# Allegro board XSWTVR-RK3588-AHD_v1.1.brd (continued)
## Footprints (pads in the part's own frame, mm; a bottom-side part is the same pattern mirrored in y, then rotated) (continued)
IC_SOT_223_1P2V
  rect 2.2x1.1 smd: 1(3.099,-2.3) 2(3.099,0) 3(3.099,2.3)
  rect 2.2x3.5 smd: 4(-3.099,0)
IC_SSOP_16
  oval 0.574x2.038 smd: 1(-4.445,-2.769) 2(-3.175,-2.769) 3(-1.905,-2.769) 4(-0.635,-2.769) 5(0.635,-2.769) 6(1.905,-2.769) 7(3.175,-2.769) 8(4.445,-2.769) 9(4.445,2.769) 10(3.175,2.769) 11(1.905,2.769) 12(0.635,2.769) 13(-0.635,2.769) 14(-1.905,2.769) 15(-3.175,2.769) 16(-4.445,2.769)
IC_TQFP128
  oval 0.3x1.5 smd: 1(-6.25,-7.75) 32(6.25,-7.75) 65(6.25,7.75) 96(-6.25,7.75)
  oval 0.2x1.5 smd: 2(-5.8,-7.75) 3(-5.4,-7.75) 4(-5,-7.75) 5(-4.6,-7.75) 6(-4.2,-7.75) 7(-3.8,-7.75) 8(-3.4,-7.75) 9(-3,-7.75) 10(-2.6,-7.75) 11(-2.2,-7.75) 12(-1.8,-7.75) 13(-1.4,-7.75) 14(-1,-7.75) 15(-0.6,-7.75) 16(-0.2,-7.75) 17(0.2,-7.75) 18(0.6,-7.75) 19(1,-7.75) 20(1.4,-7.75) 21(1.8,-7.75) 22(2.2,-7.75) 23(2.6,-7.75) 24(3,-7.75) 25(3.4,-7.75) 26(3.8,-7.75) 27(4.2,-7.75) 28(4.6,-7.75) 29(5,-7.75) 30(5.4,-7.75) 31(5.8,-7.75) 66(5.8,7.75) 67(5.4,7.75) 68(5,7.75) 69(4.6,7.75) 70(4.2,7.75) 71(3.8,7.75) 72(3.4,7.75) 73(3,7.75) 74(2.6,7.75) 75(2.2,7.75) 76(1.8,7.75) 77(1.4,7.75) 78(1,7.75) 79(0.6,7.75) 80(0.2,7.75) 81(-0.2,7.75) 82(-0.6,7.75) 83(-1,7.75) 84(-1.4,7.75) 85(-1.8,7.75) 86(-2.2,7.75) 87(-2.6,7.75) 88(-3,7.75) 89(-3.4,7.75) 90(-3.8,7.75) 91(-4.2,7.75) 92(-4.6,7.75) 93(-5,7.75) 94(-5.4,7.75) 95(-5.8,7.75)
  oval 1.5x0.3 smd: 33(7.75,-6.25) 64(7.75,6.25) 97(-7.75,6.25) 128(-7.75,-6.25)
  oval 1.5x0.2 smd: 34(7.75,-5.8) 35(7.75,-5.4) 36(7.75,-5) 37(7.75,-4.6) 38(7.75,-4.2) 39(7.75,-3.8) 40(7.75,-3.4) 41(7.75,-3) 42(7.75,-2.6) 43(7.75,-2.2) 44(7.75,-1.8) 45(7.75,-1.4) 46(7.75,-1) 47(7.75,-0.6) 48(7.75,-0.2) 49(7.75,0.2) 50(7.75,0.6) 51(7.75,1) 52(7.75,1.4) 53(7.75,1.8) 54(7.75,2.2) 55(7.75,2.6) 56(7.75,3) 57(7.75,3.4) 58(7.75,3.8) 59(7.75,4.2) 60(7.75,4.6) 61(7.75,5) 62(7.75,5.4) 63(7.75,5.8) 98(-7.75,5.8) 99(-7.75,5.4) 100(-7.75,5) 101(-7.75,4.6) 102(-7.75,4.2) 103(-7.75,3.8) 104(-7.75,3.4) 105(-7.75,3) 106(-7.75,2.6) 107(-7.75,2.2) 108(-7.75,1.8) 109(-7.75,1.4) 110(-7.75,1) 111(-7.75,0.6) 112(-7.75,0.2) 113(-7.75,-0.2) 114(-7.75,-0.6) 115(-7.75,-1) 116(-7.75,-1.4) 117(-7.75,-1.8) 118(-7.75,-2.2) 119(-7.75,-2.6) 120(-7.75,-3) 121(-7.75,-3.4) 122(-7.75,-3.8) 123(-7.75,-4.2) 124(-7.75,-4.6) 125(-7.75,-5) 126(-7.75,-5.4) 127(-7.75,-5.8)
  rect 6.35x6.35 smd: 129(0,0)
IC_WQFN_10
  rect 0.2x0.75 smd: 1(-0.2,-0.565)
  rect 0.2x0.665 smd: 2(0.2,-0.608) 6(0.2,0.608) 7(-0.2,0.608)
  rect 0.665x0.2 smd: 3(0.832,-0.4) 4(0.832,0) 5(0.832,0.4) 8(-0.832,0.4) 9(-0.832,0) 10(-0.832,-0.4)
L0402
  rect 0.5x0.5 smd: 1(-0.4,0) 2(0.4,0)
L2520
  rect 0.85x2 smd: 1(-1.15,0) 2(1.15,0)
L_6030
  rect 2.15x3.32 smd: 1(-2.913,0) 2(2.913,0)
LED_0603
  rect 0.8x0.8 smd: 1(-0.75,0) 2(0.75,0)
LEDX2
  rect 1.524x1.524 hole 0.66: 1(0,0) 3(0,-2.5)
  round 1.524 hole 0.66: 2(2.5,0) 4(2.5,-2.5)
M2_M_KEY
  rect 0.3x1.55 smd: 1(-9.25,5.275) 2(-9,-2.275) 3(-8.75,5.275) 4(-8.5,-2.275) 5(-8.25,5.275) 6(-8,-2.275) 7(-7.75,5.275) 8(-7.5,-2.275) 9(-7.25,5.275) 10(-7,-2.275) 11(-6.75,5.275) 20(-4.5,-2.275) 21(-4.25,5.275) 22(-4,-2.275) 23(-3.75,5.275) 24(-3.5,-2.275) 25(-3.25,5.275) 26(-3,-2.275) 27(-2.75,5.275) 28(-2.5,-2.275) 29(-2.25,5.275) 30(-2,-2.275) 31(-1.75,5.275) 32(-1.5,-2.275) 33(-1.25,5.275) 34(-1,-2.275) 35(-0.75,5.275) 36(-0.5,-2.275) 37(-0.25,5.275) 38(0,-2.275) 39(0.25,5.275) 40(0.5,-2.275) 41(0.75,5.275) 42(1,-2.275) 43(1.25,5.275) 44(1.5,-2.275) 45(1.75,5.275) 46(2,-2.275) 47(2.25,5.275) 48(2.5,-2.275) 49(2.75,5.275) 50(3,-2.275) 51(3.25,5.275) 52(3.5,-2.275) 53(3.75,5.275) 54(4,-2.275) 55(4.25,5.275) 56(4.5,-2.275) 57(4.75,5.275) 58(5,-2.275) 59(5.25,5.275) 60(5.5,-2.275) 61(5.75,5.275) 62(6,-2.275) 63(6.25,5.275) 64(6.5,-2.275) 65(6.75,5.275) 66(7,-2.275) 67(7.25,5.275) 68(7.5,-2.275) 69(7.75,5.275) 70(8,-2.275) 71(8.25,5.275) 72(8.5,-2.275) 73(8.75,5.275) 74(9,-2.275) 75(9.25,5.275)
  rect 1.2x2.75 smd: 76(-10.35,4.5) 77(10.35,4.5)
  round 4.5 hole 3.5: 78(0,-49.8)
M2_SSD_2240_2280
  rect 0.3x1.55 smd: 1(0.75,5.278) 2(1,-2.272) 3(1.25,5.278) 4(1.5,-2.272) 5(1.75,5.278) 6(2,-2.272) 7(2.25,5.278) 8(2.5,-2.272) 9(2.75,5.278) 10(3,-2.272) 11(3.25,5.278) 12(3.5,-2.272) 13(3.75,5.278) 14(4,-2.272) 15(4.25,5.278) 16(4.5,-2.272) 17(4.75,5.278) 18(5,-2.272) 19(5.25,5.278) 20(5.5,-2.272) 21(5.75,5.278) 22(6,-2.272) 23(6.25,5.278) 24(6.5,-2.272) 25(6.75,5.278) 26(7,-2.272) 27(7.25,5.278) 28(7.5,-2.272) 29(7.75,5.278) 30(8,-2.272) 31(8.25,5.278) 32(8.5,-2.272) 33(8.75,5.278) 34(9,-2.272) 35(9.25,5.278) 36(9.5,-2.272) 37(9.75,5.278) 38(10,-2.272) 39(10.25,5.278) 40(10.5,-2.272) 41(10.75,5.278) 42(11,-2.272) 43(11.25,5.278) 44(11.5,-2.272) 45(11.75,5.278) 46(12,-2.272) 47(12.25,5.278) 48(12.5,-2.272) 49(12.75,5.278) 50(13,-2.272) 51(13.25,5.278) 52(13.5,-2.272) 53(13.75,5.278) 54(14,-2.272) 55(14.25,5.278) 56(14.5,-2.272) 57(14.75,5.278) 58(15,-2.272) 67(17.25,5.278) 68(17.5,-2.272) 69(17.75,5.278) 70(18,-2.272) 71(18.25,5.278) 72(18.5,-2.272) 73(18.75,5.278) 74(19,-2.272) 75(19.25,5.278)
  rect 1.2x2.75 smd: 76(-0.35,4.503) 77(20.35,4.503)
  round 6 hole 3.5: 78(10.2,-40.247) 79(10.2,-78.247)
MARK
  round 1 smd: 1(0,0)
MODEL_SKG123NR
  rect 1.9x0.8 smd: 1(-6.1,8.1) 2(-6.1,7) 3(-6.1,5.9) 4(-6.1,4.8) 5(-6.1,3.7) 6(-6.1,2.6) 7(-6.1,1.5) 8(-6.1,-1.5) 9(-6.1,-2.6) 10(-6.1,-3.7) 11(-6.1,-4.8) 12(-6.1,-5.9) 13(6.1,-5.9) 14(6.1,-4.8) 15(6.1,-3.7) 16(6.1,-2.6) 17(6.1,-1.5) 18(6.1,1.5) 19(6.1,2.6) 20(6.1,3.7) 21(6.1,4.8) 22(6.1,5.9) 23(6.1,7) 24(6.1,8.1)
MODLE_65X65MM_256P
  oval 0.7x1.2 smd: 1(0,0) 64(63,0.044)
  oval 0.7x2 smd: 2(1,0.03) 3(2,0.03) 4(3,0.03) 5(4,0.03) 6(5,0.03) 7(6,0.03) 8(7,0.03) 9(8,0.03) 10(9,0.03) 11(10,0.03) 12(11,0.03) 13(12,0.03) 14(13,0.03) 15(14,0.03) 16(15,0.03) 17(16,0.03) 18(17,0.03) 19(18,0.03) 20(19,0.03) 21(20,0.03) 22(21,0.03) 23(22,0.03) 24(23,0.03) 25(24,0.03) 26(25,0.03) 27(26,0.03) 28(27,0.03) 29(28,0.03) 30(29,0.03) 31(30,0.03) 32(31,0.03) 33(32,0.03) 34(33,0.03) 35(34,0.03) 36(35,0.03) 37(36,0.03) 38(37,0.03) 39(38,0.03) 40(39,0.03) 41(40,0.03) 42(41,0.03) 43(42,0.03) 44(43,0.03) 45(44,0.03) 46(45,0.03) 47(46,0.03) 48(47,0.03) 49(48,0.03) 50(49,0.03) 51(50,0.03) 52(51,0.03) 53(52,0.03) 54(53,0.03) 55(54,0.03) 56(55,0.03) 57(56,0.03) 58(57,0.03) 59(58,0.03) 60(59,0.03) 61(60,0.03) 62(61,0.03) 63(62,0.03) 130(62,65.13) 131(61,65.13) 132(60,65.13) 133(59,65.13) 134(58,65.13) 135(57,65.13) 136(56,65.13) 137(55,65.13) 138(54,65.13) 139(53,65.13) 140(52,65.13) 141(51,65.13) 142(50,65.13) 143(49,65.13) 144(48,65.13) 145(47,65.13) 146(46,65.13) 147(45,65.13) 148(44,65.13) 149(43,65.13) 150(42,65.13) 151(41,65.13) 152(40,65.13) 153(39,65.13) 154(38,65.13) 155(37,65.13) 156(36,65.13) 157(35,65.13) 158(34,65.13) 159(33,65.13) 160(32,65.13) 161(31,65.13) 162(30,65.13) 163(29,65.13) 164(28,65.13) 165(27,65.13) 166(26,65.13) 167(25,65.13) 168(24,65.13) 169(23,65.13) 170(22,65.13) 171(21,65.13) 172(20,65.13) 173(19,65.13) 174(18,65.13) 175(17,65.13) 176(16,65.13) 177(15,65.13) 178(14,65.13) 179(13,65.13) 180(12,65.13) 181(11,65.13) 182(10,65.13) 183(9,65.13) 184(8,65.13) 185(7,65.13) 186(6,65.13) 187(5,65.13) 188(4,65.13) 189(3,65.13) 190(2,65.13) 191(1,65.13)
  oval 1.2x0.75 smd: 65(64.05,1.08) 128(64.1,64.08) 193(-1.08,64.08) 256(-1.09,1.08)
  oval 2x0.7 smd: 66(64.04,2.08) 67(64.04,3.08) 68(64.04,4.08) 69(64.04,5.08) 70(64.04,6.08) 71(64.04,7.08) 72(64.04,8.08) 73(64.04,9.08) 74(64.04,10.08) 75(64.04,11.08) 76(64.04,12.08) 77(64.04,13.08) 78(64.04,14.08) 79(64.04,15.08) 80(64.04,16.08) 81(64.04,17.08) 82(64.04,18.08) 83(64.04,19.08) 84(64.04,20.08) 85(64.04,21.08) 86(64.04,22.08) 87(64.04,23.08) 88(64.04,24.08) 89(64.04,25.08) 90(64.04,26.08) 91(64.04,27.08) 92(64.04,28.08) 93(64.04,29.08) 94(64.04,30.08) 95(64.04,31.08) 96(64.04,32.08) 97(64.04,33.08) 98(64.04,34.08) 99(64.04,35.08) 100(64.04,36.08) 101(64.04,37.08) 102(64.04,38.08) 103(64.04,39.08) 104(64.04,40.08) 105(64.04,41.08) 106(64.04,42.08) 107(64.04,43.08) 108(64.04,44.08) 109(64.04,45.08) 110(64.04,46.08) 111(64.04,47.08) 112(64.04,48.08) 113(64.04,49.08) 114(64.04,50.08) 115(64.04,51.08) 116(64.04,52.08) 117(64.04,53.08) 118(64.04,54.08) 119(64.04,55.08) 120(64.04,56.08) 121(64.04,57.08) 122(64.04,58.08) 123(64.04,59.08) 124(64.04,60.08) 125(64.04,61.08) 126(64.04,62.08) 127(64.04,63.08) 194(-1.03,63.08) 195(-1.03,62.08) 196(-1.03,61.08) 197(-1.03,60.08) 198(-1.03,59.08) 199(-1.03,58.08) 200(-1.03,57.08) 201(-1.03,56.08) 202(-1.03,55.08) 203(-1.03,54.08) 204(-1.03,53.08) 205(-1.03,52.08) 206(-1.03,51.08) 207(-1.03,50.08) 208(-1.03,49.08) 209(-1.03,48.08) 210(-1.03,47.08) 211(-1.03,46.08) 212(-1.03,45.08) 213(-1.03,44.08) 214(-1.03,43.08) 215(-1.03,42.08) 216(-1.03,41.08) 217(-1.03,40.08) 218(-1.03,39.08) 219(-1.03,38.08) 220(-1.03,37.08) 221(-1.03,36.08) 222(-1.03,35.08) 223(-1.03,34.08) 224(-1.03,33.08) 225(-1.03,32.08) 226(-1.03,31.08) 227(-1.03,30.08) 228(-1.03,29.08) 229(-1.03,28.08) 230(-1.03,27.08) 231(-1.03,26.08) 232(-1.03,25.08) 233(-1.03,24.08) 234(-1.03,23.08) 235(-1.03,22.08) 236(-1.03,21.08) 237(-1.03,20.08) 238(-1.03,19.08) 239(-1.03,18.08) 240(-1.03,17.08) 241(-1.03,16.08) 242(-1.03,15.08) 243(-1.03,14.08) 244(-1.03,13.08) 245(-1.03,12.08) 246(-1.03,11.08) 247(-1.03,10.08) 248(-1.03,9.08) 249(-1.03,8.08) 250(-1.03,7.08) 251(-1.03,6.08) 252(-1.03,5.08) 253(-1.03,4.08) 254(-1.03,3.08) 255(-1.03,2.08)
  oval 0.75x1.2 smd: 129(63,65.13) 192(0,65.15)
QFN28_4R00X4R00X0R90_T
  oval 0.23x0.665 smd: 1(-1.349,-1.932) 2(-0.899,-1.932) 3(-0.449,-1.932) 4(0.001,-1.932) 5(0.451,-1.932) 6(0.901,-1.932) 7(1.351,-1.932) 15(1.351,1.932) 16(0.901,1.932) 17(0.451,1.932) 18(0.001,1.932) 19(-0.449,1.932) 20(-0.899,1.932) 21(-1.349,1.932)
  oval 0.665x0.23 smd: 8(1.932,-1.351) 9(1.932,-0.901) 10(1.932,-0.451) 11(1.932,-0.001) 12(1.932,0.449) 13(1.932,0.899) 14(1.932,1.349) 22(-1.932,1.349) 23(-1.932,0.899) 24(-1.932,0.449) 25(-1.932,-0.001) 26(-1.932,-0.451) 27(-1.932,-0.901) 28(-1.932,-1.351)
  rect 2.4x2.4 smd: 29(0,0)
QFN40_5R00X5R00X0R90_T
  rect 0.65x0.231 smd: 1(-2.4,1.801) 2(-2.4,1.399) 3(-2.4,1.001) 4(-2.4,0.599) 5(-2.4,0.201) 6(-2.4,-0.201) 7(-2.4,-0.599) 8(-2.4,-1.001) 9(-2.4,-1.399) 10(-2.4,-1.801) 21(2.4,-1.801) 22(2.4,-1.399) 23(2.4,-1.001) 24(2.4,-0.599) 25(2.4,-0.201) 26(2.4,0.201) 27(2.4,0.599) 28(2.4,1.001) 29(2.4,1.399) 30(2.4,1.801)
  rect 0.231x0.65 smd: 11(-1.801,-2.4) 12(-1.399,-2.4) 13(-1.001,-2.4) 14(-0.599,-2.4) 15(-0.201,-2.4) 16(0.201,-2.4) 17(0.599,-2.4) 18(1.001,-2.4) 19(1.399,-2.4) 20(1.801,-2.4) 31(1.801,2.4) 32(1.399,2.4) 33(1.001,2.4) 34(0.599,2.4) 35(0.201,2.4) 36(-0.201,2.4) 37(-0.599,2.4) 38(-1.001,2.4) 39(-1.399,2.4) 40(-1.801,2.4)
  rect 3.5x3.5 smd: 41(0,0)
R0201
  rect 0.3x0.35 smd: 1(-0.249,0) 2(0.249,0)
R0402
  rect 0.5x0.6 smd: 1(-0.5,0) 2(0.5,0)
R0603
  rect 1.016x0.813 smd: 1(-0.762,0) 2(0.762,0)
R0805
  rect 1.001x1.199 smd: 1(-1,0) 2(1,0)
R1206
  rect 1.208x1.701 smd: 1(-1.479,0) 2(1.479,0)
SIM_002_P6
  rect 0.9x1.34 smd: C1(-5.16,7.562) C2(-2.62,7.562) C3(-0.08,7.562) C5(-6.43,7.562) C6(-3.89,7.562) C7(-1.35,7.562)
  rect 1.35x2.6 smd: C8(-7.98,5.038) C9(7.98,5.038) C10(-7.98,-7.562) C11(7.98,-7.562)
SMD_2P_5P4X2P9MM
  rect 0.76x1.27 smd: 1(0,3.81) 2(0,-3.81)
SMD_D6_3XL7_7
  rect 3.5x1.2 smd: 1(-2.67,0) 2(2.67,0)
SMD_D8XL10_5MM
  rect 4.6x1.6 smd: 1(-3.724,0) 2(3.724,0)
SOCKET_2X4_2P54MM
  round 1.4 hole 1: 1(3.81,-1.27) 2(3.81,1.27) 3(1.27,-1.27) 4(1.27,1.27) 5(-1.27,-1.27) 6(-1.27,1.27) 7(-3.81,-1.27) 8(-3.81,1.27)
SOCKET_4P_2P54
  rect 1.7x1.7 hole 1.1: 1(-3.75,0)
  round 1.7 hole 1.1: 2(-1.25,0) 3(1.25,0) 4(3.75,0)
SOCKET_PLUG_0366380002
  round 1.6 hole 1.1: A1(14.85,-6) A2(14.85,-2) A3(14.85,2) A4(14.85,6) B1(12.35,-6) B2(12.35,-2) B3(12.35,2) B4(12.35,6) C1(9.85,-6) C2(9.85,-2) C3(9.85,2) C4(9.85,6) D1(7.35,-6) D2(7.35,-2) D3(7.35,2) D4(7.35,6) E1(4.85,-6) E2(4.85,-2) E3(4.85,2) E4(4.85,6) F1(2.35,-6) F2(2.35,-2) F3(2.35,2) F4(2.35,6) G1(-0.15,-6) G2(-0.15,-2) G3(-0.15,2) G4(-0.15,6) H1(-2.65,-6) H2(-2.65,-2) H3(-2.65,2) H4(-2.65,6) J1(-5.15,-6) J2(-5.15,-2) J3(-5.15,2) J4(-5.15,6) K1(-7.65,-6) K2(-7.65,-2) K3(-7.65,2) K4(-7.65,6) L1(-11.15,-6) L2(-11.15,-2) L3(-11.15,2) L4(-11.15,6) M1(-14.85,-6) M2(-14.85,-2) M3(-14.85,2) M4(-14.85,6)
SOD_123
  rect 0.8x0.8 smd: 1(-1.705,0) 2(1.705,0)
SOD_323
  rect 0.9x0.65 smd: 1(-1.173,0) 2(1.173,0)
SOIC24_17R53X12R20X5R51
  oval 0.76x1.95 smd: 1(-6.99,-7.303)
  rect 0.76x1.95 smd: 2(-5.72,-7.303) 3(-4.45,-7.303) 4(-3.18,-7.303) 5(-1.91,-7.303) 6(-0.64,-7.303) 7(0.64,-7.303) 8(1.91,-7.303) 9(3.18,-7.303) 10(4.45,-7.303) 11(5.72,-7.303) 12(6.985,-7.303) 13(6.985,7.303) 14(5.72,7.303) 15(4.45,7.303) 16(3.18,7.303) 17(1.91,7.303) 18(0.64,7.303) 19(-0.64,7.303) 20(-1.91,7.303) 21(-3.18,7.303) 22(-4.45,7.303) 23(-5.72,7.303) 24(-6.99,7.303)
SON10_2R50X1R00X0R50
  rect 0.2x0.68 smd: 1(-1,-0.437) 2(-0.5,-0.437) 4(0.5,-0.437) 5(1,-0.437) 6(1,0.437) 7(0.5,0.437) 9(-0.5,0.437) 10(-1,0.437)
  rect 0.4x0.75 smd: 3(-0.025,-0.457) 8(-0.025,0.432)
SOT_23
  rect 1.25x0.7 smd: 1(1.25,-0.95) 2(1.25,0.95) 3(-1.25,0)
SOT_23_5
  rect 0.508x1.016 smd: 1(-0.95,-1.3) 2(0,-1.3) 3(0.95,-1.3) 4(0.95,1.3) 5(-0.95,1.3)
SOT_323
  rect 0.7x0.9 smd: 1(-0.65,-0.95) 2(0.65,-0.95) 3(0,0.95)
SW_3P95MM_3P0MM
  rect 1.05x2 smd: 1(-2.225,0) 2(2.225,0)
T_3528
  rect 1.506x2.376 smd: 1(-1.861,0) 2(1.861,0)
TF9_TFP09-2-12B
  round 1.016 hole 1.016 unplated: (-4.94,-5.217) (3.061,-5.217)
  rect 0.711x1.8 smd: 1(2.261,5.283) 2(1.161,5.283) 3(0.061,5.283) 4(-1.039,5.283) 5(-2.139,5.283) 6(-3.239,5.283) 7(-4.338,5.283) 8(-5.438,5.283) 9(-6.538,5.283)
  rect 1.626x1.422 smd: 10(6.86,4.783)
  rect 1.219x2.235 smd: 11(7.76,-4.816) 13(-7.739,-4.816)
  rect 1.219x1.422 smd: 12(-7.739,4.783)
TP_0R70
  round 0.7 smd: 1(0,0)
TP_1_0
  round 0.8 smd: 1(0,0)
USB30A9_25R70X7R32X13R85
  round 1.1 hole 0.701: 1(-3.5,-0.899) 2(-1.001,-0.899) 3(1.001,-0.899) 4(3.5,-0.899) 5(4,0.899) 6(1.999,0.899) 7(0,0.899) 8(-1.999,0.899) 9(-4,0.899)
  oval 2.499x1.199 hole 2.2x0.899: 10(-5.349,2.71) 11(-5.349,-2.71) 12(5.349,-2.71) 13(5.349,2.71)
X_3215_2P
  rect 1x1.8 smd: 1(-1.25,0) 2(1.25,0)
X_3225
  rect 1.4x1.2 smd: 1(-1.1,-0.85) 2(1.1,-0.85) 3(1.1,0.85) 4(-1.1,0.85)
X_3225_2P
  rect 1.6x2.2 smd: 1(-1.2,0) 2(1.2,0)

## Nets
1V2_PLL: C152.1 C153.1 FB13.2 U11.113
1V2_PLL1: C212.1 C213.1 FB22.2 U13.113
1V2A_V1: C161.1 C162.1 FB15.2 U11.8 U11.14
1V2A_V2: C163.1 C164.1 FB16.2 U11.20 U11.26
1V2A_V3: C165.1 C166.1 FB17.2 U11.38 U11.66
1V2A_V4: C150.1 C151.1 FB12.2 U11.92
1V2A_V5: C210.1 C211.1 FB21.2 U13.8 U13.14
1V2A_V6: C221.1 C222.1 FB24.2 U13.20 U13.26
1V2A_V7: C223.1 C224.1 FB25.2 U13.38 U13.66
1V2A_V8: C225.1 C226.1 FB26.2 U13.92
1V2D: C154.1 C155.1 C156.1 C157.1 C158.1 C159.1 C160.1 FB14.2 U11.5 U11.43 U11.48 U11.53 U11.59 U11.65 U11.78 U11.80 U11.93 U11.102 U11.112 U11.114 U11.124
1V2D1: C214.1 C215.1 C216.1 C217.1 C218.1 C219.1 C220.1 FB23.2 U13.5 U13.43 U13.48 U13.53 U13.59 U13.65 U13.78 U13.80 U13.93 U13.102 U13.112 U13.114 U13.124
3V3A_AHD1: C138.1 C139.1 C140.1 C141.1 C142.1 FB10.2 U11.11 U11.17 U11.23 U11.29 U11.37 U11.39 U11.67 U11.91
3V3A_AHD2: C198.1 C199.1 C200.1 C201.1 C202.1 FB19.2 U13.11 U13.17 U13.23 U13.29 U13.37 U13.39 U13.67 U13.91
3V3D_AHD1: C143.1 C144.1 C145.1 C146.1 C147.1 C148.1 C149.1 FB11.2 R86.1 U11.2 U11.42 U11.51 U11.58 U11.64 U11.79 U11.96 U11.100 U11.107 U11.115 U11.123 U11.128
3V3D_AHD2: C203.1 C204.1 C205.1 C206.1 C207.1 C208.1 C209.1 FB20.2 R106.2 R107.1 R109.1 R110.1 U13.2 U13.42 U13.51 U13.58 U13.64 U13.79 U13.96 U13.100 U13.107 U13.115 U13.123 U13.128
DGND: C2.2 C3.2 C4.2 C5.2 C6.2 C7.2 C8.2 C9.2 C10.2 C11.2 C12.2 C13.2 C15.2 C16.2 C17.2 C18.2 C19.2 C20.2 C21.2 C22.2 C23.2 C24.2 C25.2 C26.2 C27.2 C28.2 C29.2 C31.2 C32.2 C33.2 C34.2 C35.2 C36.2 C37.2 C38.2 C39.2 C40.2 C41.2 C42.2 C43.2 C44.2 C45.2 C51.2 C52.1 C56.1 C57.2 C60.2 C61.2 C62.2 C63.2 C64.2 C65.2 C66.2 C67.2 C68.2 C69.2 C70.2 C71.2 C72.2 C73.2 C74.2 C75.2 C76.1 C79.2 C80.1 C81.1 C82.1 C83.1 C84.1 C87.2 C88.2 C89.2 C91.2 C92.2 C96.2 C97.2 C98.2 C99.2 C100.2 C105.2 C107.2 C109.2 C110.2 C113.1 C116.1 C117.1 C125.2 C126.1 C127.1 C128.1 C129.1 C131.2 C132.2 C133.1 C134.2 C135.2 C136.2 C137.2 C138.2 C139.2 C140.2 C141.2 C142.2 C143.2 C144.2 C145.2 C146.2 C147.2 C148.2 C149.2 C150.2 C151.2 C152.2 C153.2 C154.2 C155.2 C156.2 C157.2 C158.2 C159.2 C160.2 C161.2 C162.2 C163.2 C164.2 C165.2 C166.2 C167.2 C168.2 C169.2 C170.2 C171.2 C172.2 C173.2 C174.2 C182.1 C184.1 C188.1 C189.1 C190.1 C191.2 C192.1 C193.1 C195.1 C196.2 C197.2 C198.2 C199.2 C200.2 C201.2 C202.2 C203.2 C204.2 C205.2 C206.2 C207.2 C208.2 C209.2 C210.2 C211.2 C212.2 C213.2 C214.2 C215.2 C216.2 C217.2 C218.2 C219.2 C220.2 C221.2 C222.2 C223.2 C224.2 C225.2 C226.2 C227.2 C228.2 C229.2 C230.2 C231.2 C232.2 C233.2 C234.2 C244.2 C247.2 C248.2 C249.2 C250.2 C251.2 C252.2 C253.2 C254.2 C255.2 C256.1 C257.1 C258.2 C259.2 C260.2 C261.2 C262.2 C263.2 C264.2 C265.2 C266.2 C267.2 C268.2 C269.2 C270.2 C271.2 C272.2 C273.2 C274.2 C275.2 C276.2 C277.2 C278.2 C279.2 C280.2 C281.2 C282.2 C283.2 C284.2 C285.2 C286.2 C287.2 C288.2 C289.2 C290.2 C291.2 C292.2 C293.2 C294.2 C295.2 C296.2 C297.2 C298.2 C299.2 C300.2 C301.2 C302.2 C303.2 C304.2 C305.2 C306.2 C307.2 C308.2 C310.2 C311.2 C312.2 C314.2 C321.2 C322.2 C323.2 C324.2 C325.2 C327.2 C328.1 C330.2 C331.2 C332.2 C333.2 C334.2 C335.2 C336.2 C337.2 C338.2 C339.2 C340.2 C341.2 C342.2 C348.2(B) C349.2(B) C350.1 C359.2 C360.2 C361.2 C362.2 C365.2 C366.2 C367.2 C368.1 C369.2 C370.2 C371.1 C372.2 C373.2 C374.2 C375.1 C378.2 C379.1 D1.2 D3.2 D6.2 D7.2 D8.2 D9.2 D10.2 D11.2 D12.2 D13.2 D14.2 D15.2 D16.2 D17.2 D18.2 D23.2 D26.2 D27.2 D28.2 D29.2 D30.2 D31.2 D32.2 D33.2 D34.2 D35.2 D36.2 D37.2 D38.2 D39.2 D40.2 D41.2 ED1.1 ED2.3 ED2.8 ED3.3 ED3.8 ED4.2 ED5.2 ED6.2 ED7.2 ED8.2 ED9.2 ED10.2 ED11.2 ED12.2 ED13.2 ED14.2 ED19.2 ED20.2 ED21.2 ED22.2 ED23.2 ED24.2 ED25.2 ED26.2 ED27.2 ED28.2 ED29.2 ED30.2 ED31.2 ED32.2 ED33.2 ED34.2 ED35.2 ED36.2 ED37.2 ED38.2 ED39.2 ED40.2 ED41.2 ED42.2 ED43.2 ED44.2 ED45.1 ED46.2 ED47.2 ED48.2 ED49.2 ED50.2 J1.4 J2.1 J2.3 J2.5 J2.11 J2.21 J2.27 J2.33 J2.39 J2.45 J2.51 J2.57 J2.71 J2.73 J2.75 J2.76 J2.77 J2.78 J4.C5 J4.C8 J4.C9 J4.C10 J4.C11 J9.2 J9.3 J9.4 J9.6 J9.7 J10.2 J10.3 J10.4 J10.6 J10.7 J11.2 J11.3 J11.4 J11.6 J11.7 J12.2 J12.3 J12.4 J12.6 J12.7 J13.2 J13.3 J13.4 J13.6 J13.7 J14.2 J14.3 J14.4 J14.6 J14.7 J15.2 J15.3 J15.4 J15.6 J15.7 J16.2 J16.3 J16.4 J16.6 J16.7 J17.2 J17.5 J17.8 J17.11 J17.17 J17.20 J17.21 J17.22 J17.23 J18.5 J18.6 J18.7 J18.8 J20.4 J20.7 J20.10 J20.11 J20.12 J20.13 J21.4 J21.7 J21.10 J21.11 J21.12 J21.13 J22.6(VSS) J22.10 J22.11 J22.12 J22.13 J23.4 J24.30 J24.31 J24.32(GND12) K1.1 Q1.2(EMITTER) Q4.2(EMITTER) Q5.2(EMITTER) Q6.2(E) Q10.2(SOURCE) Q11.2(SOURCE) Q12.2(E) Q14.2(E) Q15.2(E) Q16.2(E) Q17.2(E) Q18.2(E) Q19.2(E) Q20.2(E) Q21.2(E) Q22.2(E) Q23.2(E) Q24.2(E) Q25.2(E) Q26.2(E) Q27.2(E) Q28.2(E) Q29.2(E) Q30.2(S) R6.1 R7.1 R8.1 R14.1 R16.1 R17.1 R18.1 R24.1 R25.1 R26.1 R31.2 R40.1 R56.2 R69.2 R70.2 R73.2 R76.2 R77.1 R78.1 R79.1 R80.1 R81.2 R82.2 R87.1 R90.2 R93.2 R94.1 R95.1 R96.1 R97.2 R98.1 R99.2 R104.2 R108.1 R111.1 R122.1 R136.2 R140.2 R156.2 R157.2 R159.2 R161.2 R162.2 R163.2 R165.2 R166.2 R168.2 R170.2 R173.2 R186.2 R199.2 R200.2 R202.2 R204.2 R205.2 R207.2 R209.2 R210.2 R212.2 R214.2 R217.2 R235.2 R238.2 R248.1 R250.1 R282.2 R283.2 R284.2 R285.2 R298.2 R299.2 R300.2 R301.2 R305.1 R329.1 R331.2 R343.2 R350.1 R352.1 R354.1 R356.1 R358.1 R360.1 SW1.2 SW3.1 TP4.1(TP) TP6.1(TP) U1.40 U1.71 U1.149 U1.150 U2.7 U2.9 U3.7 U3.9 U4.2 U5.7 U5.9 U6.2 U8.12 U8.18(VSS_4) U8.31 U8.47 U8.63 U9.2 U10.2 U11.1 U11.44 U11.101 U11.103 U11.104 U11.105 U11.106 U11.108 U11.109 U11.110 U11.111 U11.118 U11.119 U11.120 U11.121 U11.122 U11.125 U11.126 U11.127 U11.129 U12.1 U13.1 U13.44 U13.101 U13.103 U13.104 U13.105 U13.106 U13.108 U13.109 U13.110 U13.111 U13.118 U13.119 U13.120 U13.121 U13.122 U13.125 U13.126 U13.127 U13.129 U14.1 U14.3 U14.4 U14.5 U14.6 U14.7 U14.8 U14.10 U14.11 U14.13 U14.23 U14.32 U14.39 U14.46 U14.48 U15.10 U15.12 U15.13 U15.24 U17.41 U19.41 U20.2 U21.1 U21.3 U21.5 U21.11 U21.19 U21.21 U21.27 U21.33 U21.39 U21.45 U21.51 U21.57 U21.69 U21.71 U21.73 U21.75 U21.76 U21.77 U21.78 U21.79 U22.25 U23.4 U23.13 U23.18 U23.29 U24.E1 U24.E3 U24.G4 U24.J3 U24.K1 U24.K4 U24.M2 U25.15 U26.2 U28.4 U29.2 Y1.2 Y2.2 Y3.2 Y3.4 Y4.2 Y4.4
VCC1V2: C136.1 C137.1 FB12.1 FB13.1 FB14.1 FB15.1 FB16.1 FB17.1 FB21.1 FB22.1 FB23.1 FB24.1 FB25.1 FB26.1 U12.2 U12.4(TAB)
VCC3V3_PHY0: C269.1 C270.1 C271.1 C272.1 C273.1 R158.1 R160.1 R172.2 R175.1 U17.11 U17.29 U17.40
VCC3V3_PHY1: C294.1 C295.1 C296.1 C298.1 C299.1 R201.1 R203.1 R206.2 R216.2 R219.1 U19.11 U19.29 U19.40
VCC3V3_SD: C323.1 C324.1 J22.4 U22.7
VCC3V3_SYS: C26.1 C107.1 C108.1 C134.1 C135.1 C257.2 C321.1 C322.1 C347.1 C349.1 C350.2(B) C365.1 C371.2 C375.2 D19.1 D21.1 D43.3 F2.1 FB4.2 FB5.2 FB9.1 FB10.1 FB11.1 FB18.1 FB19.1 FB20.1 Q3.2(SOURCE) Q7.1 R11.1 R36.1 R64.1 R112.1 R114.1 R115.1 R117.1 R130.1 R172.1 R211.1 R216.1 R270.2 R271.2 R272.2 R273.2 R274.1 R275.1 R276.1 R277.1 R286.2 R287.2 R288.2 R289.2 R290.1 R291.1 R292.1 R293.1 R302.2 R320.2 R323.2 R324.2 R349.2 TP2.1(TP) U4.1 U12.3 U22.5 U22.6 U25.16(VCC) U26.5 U28.9(VCC) U29.5
VCC3V9_5G: C105.1 C106.1 D43.1 FB1.2 FB2.2 FB3.2 Q2.2(SOURCE) R63.1 R350.2 TP1.1(TP) U1.143 U1.144 U1.145 U1.146
VCC5V0_SYS: C56.2 C75.1 C308.1 C366.1 C367.1 C369.1 C370.1 C372.1 C373.1 C374.1 D20.1 D22.1 FB6.2 FB7.2 Q9.1 R30.1 R232.1 TP3.1(TP) U6.1 U9.3 U9.10 U10.3 U10.10 U20.5 U26.3 U26.10 U29.3 U29.10
VCC5V0_USB30_HOST0: C310.1 C311.1 C312.1 J20.1(VBUS) R232.2 R236.1 U20.1(VOUT)
VCC5V_HDMI_TX0: C244.1 D22.2(K) J17.18
VCC_1V8: C27.1 ED41.1 FB27.1 R14.2 R119.2 R120.2 R133.1 R167.1 R347.1 U4.5(OUT) U24.D4
VCC_DCIN: C8.1 C9.1 C10.1 C11.1 C21.1 C22.1 C23.1 C24.1 C37.1 C38.1 C39.1 C40.1 C41.1 C42.1 C167.1 C168.1 C169.1 C170.1 C171.1 C172.1 C173.1 C174.1 C227.1 C228.1 C229.1 C230.1 C231.1 C232.1 C233.1 C234.1 D4.1(CATHODE) J9.1 J10.1 J11.1 J12.1 J13.1 J14.1 J15.1 J16.1 R13.2 R22.2 U2.2 U3.2 U5.2
VCC_IN: D4.2 ED44.1 R21.1 U24.M1
VCCA1V8_CODEC: C331.1 C332.1 C333.1 C336.1 C337.1 C341.1 C342.1 FB27.2 FB28.1 R257.2 R267.2 U23.2 U23.3 U23.16
VCCIO_PHY0: C266.1 C267.1 C268.1 R164.1 R167.2 R169.1 R171.1 R174.1 R176.1 U17.28
VCCIO_PHY1: C291.1 C292.1 C293.1 R208.1 R211.2 R213.1 R215.1 R218.1 R220.1 U19.28
VCCIO_WL: C255.1 R129.1 R133.2 U14.34
VDD10_PHY0: C275.1 C276.1 C277.1 C279.1 C280.1 C281.1 L6.2 U17.3 U17.8 U17.21 U17.38
VDD10_PHY1: C301.1 C302.1 C303.1 C305.1 C306.1 C307.1 L7.2 U19.3 U19.8 U19.21 U19.38
VINN1: C120.1 R73.1
VINN2: C121.1 R76.1
VINN3: C123.1 R81.1
VINN4: C112.1 R82.1
VINN5: C176.1 R90.1
VINN6: C178.1 R93.1
VINN7: C179.1 R99.1
VINN8: C187.1 R97.1
VINP1: C119.1 R71.2 R78.2
VINP1_COAX: D11.1 J9.5 R71.1
VINP2: C111.1 R74.2 R77.2
VINP2_COAX: D12.1 J10.5 R74.1
VINP3: C122.1 R72.2 R79.2
VINP3_COAX: D14.1 J11.5 R72.1
VINP4: C124.1 R75.2 R80.2
VINP4_COAX: D13.1 J12.5 R75.1
VINP5: C175.1 R88.2 R94.2
VINP5_COAX: D15.1 J13.5 R88.1
VINP6: C177.1 R91.2 R95.2
VINP6_COAX: D16.1 J14.5 R91.1
VINP7: C186.1 R89.2 R98.2
VINP7_COAX: D17.1 J15.5 R89.1
VINP8: C180.1 R92.2 R96.2
VINP8_COAX: D18.1 J16.5 R92.1
5G_3V3: Q3.3 R52.2 R53.2 R54.2 R345.1
5G_3V9: C79.1 C80.2 C81.2 C82.2 C83.2 C87.1 C88.1 C89.1 C91.1 C92.1 D6.1 J2.2 J2.4 J2.70 J2.72 J2.74 Q2.3
5G_PWR_OFF: J2.6 J24.3
5G_PWRER_CTR: J24.8 R67.1
5G_RESET: J24.12 R55.1
5G_USB_DM: J2.9 U28.5
5G_USB_DP: J2.7 U28.3
5G_VBUS: J21.1(VBUS) R330.1
5G_W_DISABLE1#: J2.8(W_DISABLE1#) R51.1
5G_WAKE_MCU: Q32.3 R345.2 U8.33
5G_WAKE_ON_WAN: J2.23 Q32.2(EMITTER)
5G_WAKEUP_IN: J2.38 U1.214
5G_WWAN_LED#: J2.10 R348.1
27M_CLK_XI: C132.1 R83.2 R85.1 Y1.3
27M_CLK_XI1: C197.1 R101.2 R105.1 Y2.3
ACC: R304.2 U24.C4
ACC_CHECK: ED45.2 J24.21 Q30.3 R39.2 R302.1
AHD_I2C_SCL: R107.2 U1.99 U11.49 U13.49
AHD_I2C_SDA: R106.1 U1.98 U11.50 U13.50
AHD_RSTN: U1.95 U11.47 U13.47
ARM_BOOT: ED46.1 R303.2 U24.K2
ARM_CAN0_H: ED33.1 R335.1 U24.G3
ARM_CAN0_L: ED36.1 R337.1 U24.F3
ARM_CAN1_H: ED43.1 R338.1 U24.B4
ARM_CAN1_L: ED42.1 R340.1 U24.A4
ARM_CAN2_EN: U1.100 U26.6
ARM_CAN2_NSTB: U1.97 U26.14
ARM_CAN3_EN: J24.20 U29.6
ARM_CAN3_NSTB: U1.92 U29.14
BOOT: D44.2(CATHODE) U24.B3
BOOT0: Q31.3 R343.1 U8.60
BOOT_SARADC_IN0: J24.2 R303.1
BT&WIFI_ANT: C254.1 J18.2 R132.1
BT_RST: U1.233 U14.38
BT_WAKE_HOST_H: U1.216 U14.50
CAN1_RX: U8.61 U9.4
CAN1_RX_M1: J24.19 U26.4
CAN1_TX: U8.62 U9.1
CAN1_TX_M1: J24.18 U26.1
CAN2_RX: U8.57 U10.4
CAN2_RX_M0: U1.96 U29.4
CAN2_TX: U8.58 U10.1
CAN2_TX_M0: U1.93 U29.1
CAN_WAKEUP_0: R351.1 R352.2 U8.37
CAN_WAKEUP_1: R353.1 R354.2 U8.39
CAN_WAKEUP_2: R355.1 R356.2 U8.34
CAN_WAKEUP_3: R357.1 R358.2 U8.35
CORE_INPUT1: J24.29 Q14.3 R270.1
CORE_INPUT2: J24.28 Q15.3 R271.1
CORE_INPUT3: J24.27 Q16.3 R272.1
CORE_INPUT4: J24.26 Q17.3 R273.1
CORE_OUTPUT1: D37.1 J24.25 R297.1
CORE_OUTPUT2: D38.1 J24.24 R294.1
CORE_OUTPUT3: D39.1 J24.23 R295.1
CORE_OUTPUT4: D40.1 J24.22 R296.1
DEBUG_DM: R240.2 U28.6
DEBUG_DM0: ED19.1 J21.2 R240.1
DEBUG_DP: R242.2 U28.2
DEBUG_DP0: ED20.1 J21.3 R242.1
ETH0_REFCLKO_25M: R148.1 U1.227
ETH1_REFCLKO_25M: R193.1 U1.156
GMAC0_MCLKINOUT: C264.1 R155.1 R156.1 U1.223
GMAC0_MDC: U1.250 U17.13
GMAC0_MDIO: R176.2 U1.236 U17.14
GMAC0_RSTN_L: R177.1 U1.94
GMAC0_RXCLK: C282.1 R182.2 U1.162
GMAC0_RXD0: R178.2 U1.245
GMAC0_RXD1: R179.2 U1.237
GMAC0_RXD2: R180.2 U1.165
GMAC0_RXD3: R181.2 U1.164
GMAC0_RXDV_CRS: R183.2 U1.228
GMAC0_TXCLK: C274.1 U1.163 U17.20
GMAC0_TXD0: U1.229 U17.18
GMAC0_TXD1: U1.225 U17.17
GMAC0_TXD2: U1.166 U17.16
GMAC0_TXD3: U1.167 U17.15
GMAC0_TXEN: U1.224 U17.19
GMAC1_MCLKINOUT: C289.1 R198.1 R199.1 U1.141
GMAC1_MDC: U1.153 U19.13
GMAC1_MDIO: R220.2 U1.152 U19.14
GMAC1_RSTN_L: R221.1 U1.148
GMAC1_RXCLK: C304.1 R226.2 U1.159
GMAC1_RXD0: R222.2 U1.160
GMAC1_RXD1: R223.2 U1.157
GMAC1_RXD2: R224.2 U1.171
GMAC1_RXD3: R225.2 U1.174
GMAC1_RXDV_CRS: R227.2 U1.158
GMAC1_TXCLK: C297.1 U1.161 U19.20
GMAC1_TXD0: U1.151 U19.18
GMAC1_TXD1: U1.147 U19.17
GMAC1_TXD2: U1.173 U19.16
GMAC1_TXD3: U1.172 U19.15
GMAC1_TXEN: U1.142 U19.19
GNSS_ANT: J18.1 L5.1 U15.11
GNSS_RST: J24.15 U15.8
GNSS_STATE: J24.7 R135.1
HDMI0_EARC+: C245.2 ED8.1 J17.14(UTILITY)
HDMI0_EARC-: C246.2 ED4.1 J17.19 R121.2
HDMI0_TX0N_PORT: C240.2 ED3.2 ED3.9(NC_9) J17.9
HDMI0_TX0N_PORT/EDP0_TX_D0N: C240.1 U1.16
HDMI0_TX0P_PORT: C239.2 ED3.1 ED3.10 J17.7
HDMI0_TX0P_PORT/EDP0_TX_D0P: C239.1 U1.17
HDMI0_TX1N_PORT: C238.2 ED2.5 ED2.6 J17.6
HDMI0_TX1N_PORT/EDP0_TX_D1N: C238.1 U1.18
HDMI0_TX1P_PORT: C237.2 ED2.4 ED2.7 J17.4
HDMI0_TX1P_PORT/EDP0_TX_D1P: C237.1 U1.19
HDMI0_TX2N_PORT: C236.2 ED2.2 ED2.9(NC_9) J17.3
HDMI0_TX2N_PORT/EDP0_TX_D2N: C236.1 U1.20
HDMI0_TX2P_PORT: C235.2 ED2.1 ED2.10 J17.1
HDMI0_TX2P_PORT/EDP0_TX_D2P: C235.1 U1.21
HDMI0_TX3N_PORT: C242.2 ED3.5 ED3.6 J17.12
HDMI0_TX3N_PORT/EDP0_TX_D3N: C242.1 U1.14
HDMI0_TX3P_PORT: C241.2 ED3.4 ED3.7 J17.10
HDMI0_TX3P_PORT/EDP0_TX_D3P: C241.1 U1.15
HDMI0_TX_CEC_PORT: ED7.1 J17.13 Q9.3 R118.2
HDMI0_TX_SBDN/EDP0_TX_AUXN: C246.1 U1.12
HDMI0_TX_SBDP/EDP0_TX_AUXP: C245.1 U1.13
HDMI0_TX_SCL_PORT: ED6.1 J17.15 Q7.3 R113.2
HDMI0_TX_SDA_PORT: ED5.1 J17.16 Q8.3 R116.2
HDMITX0_CEC_M0: Q9.2(SOURCE) R117.2 U1.170
HDMITX0_HPDIN: Q10.3 R119.1 U1.231
HDMITX0_SCL_M0: Q7.2(SOURCE) R112.2 U1.168
HDMITX0_SDA_M0: C243.2 Q8.2(SOURCE) R114.2 U1.169
HOST_WAKE_BT_H: U1.218 U14.49
I2C4_SCL_M1_GPIO2-B5: J2.25 U1.211
I2C4_SDA_M1_GPIO2-B4: J2.68 U1.212
I2C_ADDR_CE: R267.1 U23.26
I2S0_LRCK_TX: R263.1 U1.220
I2S0_MCLK: R260.1 U1.222
I2S0_SCLK_TX: R261.1 U1.219
I2S0_SDI0: R264.1 U1.239
I2S0_SDO0: R262.1 U1.221
INPUT1: D33.1 ED40.1 R280.1 U24.E2
INPUT2: D34.1 ED37.1 R278.1 U24.F2
INPUT3: D35.1 ED34.1 R279.1 U24.G2
INPUT4: D36.1 ED31.1 R281.1 U24.H2
LAN0_A+: J28.1 U16.23
LAN0_A-: J28.2 U16.22
LAN0_B+: J28.3 U16.20
LAN0_B-: J28.6 U16.19
LAN0_C+: J28.4 U16.17
LAN0_C-: J28.5 U16.16
LAN0_D+: J28.7 U16.14
LAN0_D-: J28.8 U16.13
LAN0_MCT1: R153.1 U16.24
LAN0_MCT2: R152.1 U16.21
LAN0_MCT3: R151.1 U16.18
LAN0_MCT4: R150.1 U16.15
LAN1_A+: J27.1 U18.23
LAN1_A-: J27.2 U18.22
LAN1_B+: J27.3 U18.20
LAN1_B-: J27.6 U18.19
LAN1_C+: J27.4 U18.17
LAN1_C-: J27.5 U18.16
LAN1_D+: J27.7 U18.14
LAN1_D-: J27.8 U18.13
LAN1_MCT1: R197.1 U18.24
LAN1_MCT2: R196.1 U18.21
LAN1_MCT3: R195.1 U18.18
LAN1_MCT4: R194.1 U18.15
LINE_OUT_L: ED30.1 R268.2 U24.H4
LINE_OUT_R: ED29.1 R269.2 U24.J4
LMIC_CP: C326.1 C327.1 C330.1 ED39.1 R258.1 U24.E4
MCU_3V3: C46.1 C51.1 C52.2 C66.1 C67.1 C68.1 C69.1 C70.1 C71.1 C72.1 C76.2 C368.2 C377.1 F1.1 J1.1 Q31.2(EMITTER) R27.1 R341.1 R346.1 U6.6(OUT) U8.1 U8.19 U8.32 U8.48 U8.64 U9.5 U10.5
MCU_CAN0_EN: U8.38 U9.6
MCU_CAN0_H: ED38.1 R44.1 U24.F1
MCU_CAN0_L: ED35.1 R45.1 U24.G1
MCU_CAN0_NSTB: U8.36 U9.14
MCU_CAN1_EN: U8.41 U10.6
MCU_CAN1_H: ED32.1 R332.1 U24.H1
MCU_CAN1_L: ED27.1 R334.1 U24.J1
MCU_CAN1_NSTB: U8.40 U10.14
MCU_DEBUG_RX: U8.43 U25.9
MCU_DEBUG_RX1: ED48.1 J23.2 R309.2(B) U24.B2
MCU_DEBUG_TX: U8.42 U25.10
MCU_DEBUG_TX1: ED47.1 J23.3 R308.2(B) U24.B1
MCU_RST: C62.1 K1.2 R36.2 U8.7
MCU_WAKEUP_RK3588: Q33.2(EMITTER) U8.44
MIPI_CSI0_RX_CLK0N: U1.136 U11.85
MIPI_CSI0_RX_CLK0P: U1.135 U11.86
MIPI_CSI0_RX_D0N: U1.140 U11.81
MIPI_CSI0_RX_D0P: U1.139 U11.82
MIPI_CSI0_RX_D1N: U1.138 U11.83
MIPI_CSI0_RX_D1P: U1.137 U11.84
MIPI_CSI0_RX_D2N: U1.134 U11.87
MIPI_CSI0_RX_D2P: U1.133 U11.88
MIPI_CSI0_RX_D3N: U1.132 U11.89
MIPI_CSI0_RX_D3P: U1.131 U11.90
MIPI_CSI1_RX_CLK0N: U1.125 U13.85
MIPI_CSI1_RX_CLK0P: U1.126 U13.86
MIPI_CSI1_RX_D0N: U1.129 U13.81
MIPI_CSI1_RX_D0P: U1.130 U13.82
MIPI_CSI1_RX_D1N: U1.127 U13.83
MIPI_CSI1_RX_D1P: U1.128 U13.84
MIPI_CSI1_RX_D2N: U1.123 U13.87
MIPI_CSI1_RX_D2P: U1.124 U13.88
MIPI_CSI1_RX_D3N: U1.121 U13.89
MIPI_CSI1_RX_D3P: U1.122 U13.90
OSC_IN: C63.1 R38.1 U8.5 X2.1
OSC_OUT: C64.1 R38.2 U8.6 X2.2
OUTPUT1: ED23.1 Q22.3 R286.1 U24.L1
OUTPUT2: ED24.1 Q23.3 R287.1 U24.L2
OUTPUT3: ED25.1 Q24.3 R288.1 U24.L3
OUTPUT4: ED26.1 Q25.3 R289.1 U24.L4
PCIE20_0_RXN/SATA30_0_RXN: C357.1 U1.184
PCIE20_0_RXP/SATA30_0_RXP: C358.1 U1.183
PCIE20_0_TXN/SATA30_0_TXN: C355.1 U1.181
PCIE20_0_TXP/SATA30_0_TXP: C356.1 U1.182
PCIE20_2_REFCLKN: J2.53 U1.189
PCIE20_2_REFCLKP: J2.55 U1.190
PCIE20_2_RXN/SATA30_2_RXN: J2.41 U1.185
PCIE20_2_RXP/SATA30_2_RXP: J2.43 U1.186
PCIE20_2_TXN/SATA30_2_TXN: C85.1 U1.187
PCIE20_2_TXP/SATA30_2_TXP: C86.1 U1.188
PCIEX1_1_CLKREQN_M1_L: J2.52 J24.13 R53.1
PCIEX1_1_PERSTN_M1_L: J2.50 J24.11 R52.1
PCIEX1_1_WAKEN_M1_L: J2.54 J24.6 R54.1
PHY0_CLKOUT125: R155.2 U17.35
PHY0_LED0/CFG_EXT: R157.1 R158.2 U17.32
PHY0_LED1/CFG_LDO0: R161.1 U17.33
PHY0_LED2/CFG_LDO1: R159.1 R160.2 U17.34
PHY0_MDI0+: R137.1 U17.1
PHY0_MDI0-: R138.1 U17.2
PHY0_MDI1+: R141.1 U17.4
PHY0_MDI1-: R142.1 U17.5
PHY0_MDI2+: R143.1 U17.6
PHY0_MDI2-: R145.1 U17.7
PHY0_MDI3+: R146.1 U17.9
PHY0_MDI3-: R147.1 U17.10
PHY0_MDI_0+: R137.2 U16.2
PHY0_MDI_0-: R138.2 U16.3
PHY0_MDI_1+: R141.2 U16.5
PHY0_MDI_1-: R142.2 U16.6
PHY0_MDI_2+: R143.2 U16.8
PHY0_MDI_2-: R145.2 U16.9
PHY0_MDI_3+: R146.2 U16.11
PHY0_MDI_3-: R147.2 U16.12(TD4-)
PHY0_REG_OUT: L6.1 U17.30
PHY0_RSTN: C278.1 R175.2 R177.2 U17.12
PHY0_RXCLK/PHYAD1: R165.1 R182.1 U17.27
PHY0_RXD0/RXDLY: R168.1 R169.2 R178.1 U17.25
PHY0_RXD1/TXDLY: R170.1 R171.2 R179.1 U17.24
PHY0_RXD2/PLLOFF: R173.1 R174.2 R180.1 U17.23
PHY0_RXD3/PHYAD0: R163.1 R164.2 R181.1 U17.22
PHY0_RXDV/PHYAD2: R166.1 R183.1 U17.26
PHY0_XTALIN: C259.1 R140.1 U17.36 Y3.3(X2)
PHY0_XTALOUT: C258.1 R148.2 U17.37(XTAL_OUT/EXT_CLK) Y3.1
PHY1_CLKOUT125: R198.2 U19.35
PHY1_LED0/CFG_EXT: R200.1 R201.2 U19.32
PHY1_LED1/CFG_LDO0: R204.1 U19.33
PHY1_LED2/CFG_LDO1: R202.1 R203.2 U19.34
PHY1_MDI0+: R185.1 U19.1
PHY1_MDI0-: R184.1 U19.2
PHY1_MDI1+: R187.1 U19.4
PHY1_MDI1-: R188.1 U19.5
PHY1_MDI2+: R189.1 U19.6
PHY1_MDI2-: R190.1 U19.7
PHY1_MDI3+: R191.1 U19.9
PHY1_MDI3-: R192.1 U19.10
PHY1_MDI_0+: R185.2 U18.2
PHY1_MDI_0-: R184.2 U18.3
PHY1_MDI_1+: R187.2 U18.5
PHY1_MDI_1-: R188.2 U18.6
PHY1_MDI_2+: R189.2 U18.8
PHY1_MDI_2-: R190.2 U18.9
PHY1_MDI_3+: R191.2 U18.11
PHY1_MDI_3-: R192.2 U18.12(TD4-)
PHY1_REG_OUT: L7.1 U19.30
PHY1_RSTN: C300.1 R219.2 R221.2 U19.12
PHY1_RXCLK/PHYAD1: R209.1 R226.1 U19.27
PHY1_RXD0/RXDLY: R212.1 R213.2 R222.1 U19.25
PHY1_RXD1/TXDLY: R214.1 R215.2 R223.1 U19.24
PHY1_RXD2/PLLOFF: R217.1 R218.2 R224.1 U19.23
PHY1_RXD3/PHYAD0: R207.1 R208.2 R225.1 U19.22
PHY1_RXDV/PHYAD2: R210.1 R227.1 U19.26
PHY1_XTALIN: C284.1 R186.1 U19.36 Y4.3(X2)
PHY1_XTALOUT: C283.1 R193.2 U19.37(XTAL_OUT/EXT_CLK) Y4.1
POWER_EN: R6.2 U2.3 U8.21
RESET_L: ED28.1 R2.2 U24.J2
RFFE_VIO_1V8: C376.1 J2.65 R51.2 R68.1 R344.1
RM500U_RESET: C84.2 J2.67 Q1.3
RS232_RXD: ED21.1 R307.2(B) U24.M3
RS232_TXD: ED22.1 R306.2(B) U24.M4
RSET0: R162.1 U17.39
RSET1: R205.1 U19.39
RTC_IN: C60.1 U8.3 X1.1
RTC_OUT: C61.1 U8.4 X1.2
RUN_LED: D41.4 U8.45
SARADC_VIN1_KEY/RECOVERY: ED1.2 R1.1 U1.1
SATA0_RXN: C357.2 U21.43
SATA0_RXP: C358.2 U21.41(SATA_BP(RP))
SATA0_TXN: C355.2 U21.47
SATA0_TXP: C356.2 U21.49
SCL_CODEC: R265.1 U1.255
SD_CLK: R128.1 U1.11
SDA_CODEC: R266.1 U1.256
SDMMC0_CMD: R127.1 U1.10
SDMMC0_D0: R123.1 U1.6
SDMMC0_D1: R124.1 U1.7
SDMMC0_D2: R125.1 U1.8
SDMMC0_D3: R126.1 U1.9
SDMMC_CLK: R359.1 U22.18
SDMMC_CMD: R254.1 U22.20
SDMMC_D0: R255.1 U22.13
SDMMC_D1: R256.1 U22.12
SDMMC_D2: R252.1 U22.23
SDMMC_D3: R253.1 U22.22
SDMMC_DET_L: D26.1 J22.9 U22.10
SWCLK: J1.2 U8.49
SWDIO: J1.3 U8.46
TYPEC0_OTG_DM: R228.2 U1.58
TYPEC0_OTG_DP: R230.2 U1.57
TYPEC0_SSRX1N: R233.1 U1.66
TYPEC0_SSRX1P: R234.1 U1.65
TYPEC0_SSTX1N: C309.1 U1.70
TYPEC0_SSTX1P: C313.1 U1.69
TYPEC0_USB20_OTG_ID: SW3.2(B1) U1.252
TYPEC0_USB20_VBUSDET: C314.1 R236.2 R238.1 U1.60
UART1_RX_M1: J2.64 U1.240
UART1_TX_M1: J2.62 U1.241
UART2_RX_M0_DEBUG: U1.3 U25.12
UART2_TX_M0_DEBUG: U1.2 U25.11
UART3_RX_M0: J24.5 U15.20
UART3_TX_M0: J24.4 U15.21
UART6_CTSN_M1: U1.230 U14.42
UART6_RTSN_M1: U1.232 U14.43
UART6_RX_M1: U1.235 U14.40
UART6_TX_M1: U1.234 U14.41
UART7_RX_M1: ED50.1 U1.155 U24.A2
UART7_TX_M1: ED49.1 U1.154 U24.A1
UART9_RX_M1: J24.16 U8.16
UART9_TX_M1: J24.17 U8.17
USB20_HOST0_DM: U1.42 U28.7
USB20_HOST0_DP: U1.41 U28.1
USB20_HOST1_DM: U1.46 U22.3
USB20_HOST1_DP: U1.45 U22.4
USB30_HOST0_SSRXN: ED12.1 J20.5 R233.2
USB30_HOST0_SSRXP: ED11.1 J20.6 R234.2
USB30_HOST0_SSTXN: C309.2 ED10.1 J20.8
USB30_HOST0_SSTXP: C313.2 ED9.1 J20.9
USB30_OTG0_DM: ED13.1 J20.2 R229.1
USB30_OTG0_DP: ED14.1 J20.3 R231.1
USB_HOST_PWREN_H: U1.249 U20.4
USIM1_CLK: C100.1 D7.1 J2.32 J4.C3
USIM1_DATA: C99.1 D10.1 J2.34 J4.C7 R59.2
USIM1_RST: C98.1 D8.1 J2.30 J4.C2
USIM1_VDD: C96.1 C97.1 D9.1 J2.36 J4.C1 R59.1
V_ANT: L5.2 U15.9
V_DDA: C65.1 C73.1 C74.1 F1.2 U8.13
VIDEO_IND: J24.10 R102.1
WAKEUP_RK3588: Q33.3 R347.2 U1.254
WIFI1T1R_CLK: R128.2 U14.18
WIFI1T1R_CMD: R127.2 U14.17
WIFI1T1R_D0: R123.2 U14.21
WIFI1T1R_D1: R124.2 U14.22
WIFI1T1R_D2: R125.2 U14.20
WIFI1T1R_D3: R126.2 U14.19
WIFI_3V3: C247.1 C248.1 C249.1 C250.1 D23.1 R130.2 U14.36
WIFI_ANT: C252.1 J18.3 R131.1
WIFI_ANT0: C251.1 R131.2 U14.9
WIFI_ANT1: C253.1 R132.2 U14.2
WIFI_REG_ON: U1.215 U14.15
WIFI_WAKE_HOST: U1.246 U14.16(WL_WAKE_HOST)
XO: R83.1 R84.2 U11.95(XO)
XO1: R101.1 R103.2 U13.95(XO)
N16931377: Q14.1 Q18.3 R274.2
N16931417: Q18.1 R280.2 R282.1
N16931861: Q15.1 Q19.3 R275.2
N16931902: Q19.1 R278.2 R283.1
N16962772: C119.2 U11.12
N16962795: C120.2 U11.13
N16962816: C111.2 U11.18
N16962837: C121.2 U11.19
N16962856: C122.2 U11.24
N16962873: C123.2 U11.25
N16962896: C124.2 U11.30
N16962917: C112.2 U11.31
N16962947: C113.2 C114.1 U11.9
N16962991: C114.2 C127.2 U11.10
N16963001: C115.1 C126.2 U11.15
N16963037: C115.2 C116.2 U11.16
N16963051: C117.2 C118.1 U11.21
N16963101: C118.2 C129.2 U11.22
N16963115: C128.2 C130.1 U11.27
N16963147: C130.2 C133.2 U11.28
N16963702: R85.2 U11.94
N16963854: R86.2 U11.45
N16963899: R87.2 U11.46
N16974815: C125.1 FB9.2 Y1.4(VCC)
N16974853: C131.1 R84.1 Y1.1
N16985810: Q16.1 Q20.3 R276.2
N16985852: Q20.1 R279.2 R284.1
N17187928: R235.1 U20.3
N17430388: C14.1 D1.1(CATHODE) L2.1 U3.8
N17430409: C15.1 C16.1 C17.1 C18.1 C19.1 C20.1 FB4.1 FB5.1 L2.2 R9.2
N17430604: C14.2 U3.1
N17430621: R9.1 R12.2
N17430780: R13.1 R16.2 U3.3
N17430784: C28.1 R15.2 U3.6
N17430790: R12.1 R18.2 U3.5(VSENSE)
N17430830: R17.2 U3.4
N17430874: C29.1 R15.1
N17430974: C30.1 D3.1(CATHODE) L3.1 U5.8
N17430995: C31.1 C32.1 C33.1 C34.1 C35.1 C36.1 FB6.1 FB7.1 L3.2 R19.2
N17431217: C30.2 U5.1
N17431234: R19.1 R20.2
N17431430: R22.1 R24.2 U5.3
N17431436: C44.1 R23.2 U5.6
N17431442: R20.1 R26.2 U5.5(VSENSE)
N17431605: C45.1 R23.1
N17445345: C43.1 R21.2
N17445910: C1.1 L1.1 U2.8
N17445924: C2.1 C3.1 C4.1 C5.1 C6.1 C7.1 FB1.1 FB2.1 FB3.1 L1.2 R3.2
N17446104: C1.2 U2.1
N17446121: R3.1 R4.2
N17446263: C12.1 R5.2 U2.6
N17446269: R4.1 R8.2 U2.5(VSENSE)
N17446309: R7.2 U2.4
N17446353: C13.1 R5.1
N17457092: R40.2 U8.28
N17460494: TP7.1 U17.31
N17467708: R30.2 U6.3
N17467712: C46.2 R27.2 R31.1 U6.5
N17467744: C57.1 U6.4
N17473177: C85.2 J2.47
N17473180: C86.2 J2.49
N17481320: Q1.1 R55.2 R56.1
N17491651: C175.2 U13.12
N17491658: C176.2 U13.13
N17491664: C177.2 U13.18
N17491670: C178.2 U13.19
N17491675: C186.2 U13.24
N17491677: C179.2 U13.25
N17491684: C180.2 U13.30
N17491690: C187.2 U13.31
N17491701: C181.1 C188.2 U13.9
N17491710: C181.2 C189.2 U13.10
N17491714: C182.2 C183.1 U13.15
N17491717: C183.2 C184.2 U13.16
N17491723: C185.1 C190.2 U13.21
N17491731: C185.2 C192.2 U13.22
N17491737: C193.2 C194.1 U13.27
N17491742: C194.2 C195.2 U13.28
N17491772: R105.2 U13.94
N17491776: R108.2 R109.2 U13.45
N17491778: R110.2 R111.2 U13.46
N17491878: C191.1 FB18.2 Y2.4(VCC)
N17491881: C196.1 R103.1 Y2.1
N17521884: D20.2(K) R113.1 R116.1
N17521978: C243.1 Q8.1 R115.2
N17522055: D21.2(K) R118.1
N17523462: Q10.1 Q11.3 R120.1
N17523491: Q11.1 R121.1 R122.2
N17524535: D19.2(B) R100.2
N17524546: Q6.3 R100.1
N17524572: Q6.1 R102.2 R104.1
N17534566: C25.1 R11.2 U4.3
N17543240: C256.2 F2.2 U15.23
N17543343: Q12.1 R135.2 R136.1
N17556572: C285.1 U18.1
N17556623: C286.1 U18.4
N17556674: C287.1 U18.7
N17556725: C288.1 U18.10
N17556884: C290.1 R194.2 R195.2 R196.2 R197.2
N17570124: R228.1 R229.2
N17570191: R230.1 R231.2
N17583651: C343.2 R268.1
N17583654: C344.2 R269.1
N17587612: Q17.1 Q21.3 R277.2
N17587654: Q21.1 R281.2 R285.1
N17590009: Q23.1 Q26.3 R291.2
N17590020: Q24.1 Q28.3 R292.2
N17590031: Q25.1 Q29.3 R293.2
N17590042: Q22.1 Q27.3 R290.2
N17590162: Q26.1 R294.2 R299.1
N17590173: Q28.1 R295.2 R300.1
N17590184: Q29.1 R296.2 R301.1
N17590195: Q27.1 R297.2 R298.1
N17591786: C260.1 U16.1
N17591846: C261.1 U16.4
N17591906: C262.1 U16.7
N17591973: C263.1 U16.10
N17592186: C265.1 R150.2 R151.2 R152.2 R153.2
N17604176: R306.1 U25.14
N17604199: R307.1 U25.13
N17604219: C345.1 U25.3
N17604223: C345.2(B) U25.1
N17604225: C346.1 U25.4
N17604227: C346.2(B) U25.5
N17604259: C347.2(B) U25.2
N17604261: C348.1 U25.6
N17613828: R308.1 U25.7
N17613831: R309.1 U25.8
N17622103: C108.2 Q3.1 R64.2 R66.1
N17622132: Q5.3 R66.2
N17622163: C110.1 Q5.1 R68.2 R70.1
N17627462: R129.2 U14.44
N17719071: R2.1 U1.59
N17720124: R1.2 SW1.1
N17720923: Q30.1 R304.1 R305.2
N17726410: C325.1 C329.1 R257.1 R258.2
N17726460: C326.2 U23.22
N17726498: C328.2 C329.2 U23.21
N17732255: C106.2 Q2.1 R63.2 R65.1
N17732284: Q4.3 R65.2
N17732315: C109.1 Q4.1 R67.2 R69.1
N17733329: R39.1 U8.23
N17735210: D31.1 J22.2 R253.2
N17735212: D30.1 J22.3 R254.2
N17735222: D27.1 J22.8 R256.2
N17735246: D32.1 J22.1 R252.2
N17735252: D29.1 J22.5 R359.2
N17735257: D28.1 J22.7 R255.2
N17791454: C334.1 C335.1 FB28.2 U23.17
N17887677: D41.3 R323.1
N17887693: D41.1 R324.1
N17891340: R329.2 U28.8
N17893373: R330.2 R331.1 U28.10
N17901873: R43.2 R44.2 U9.13
N17901877: R43.1 R45.2 U9.12
N17904447: R332.2 R333.2 U10.13
N17904489: R333.1 R334.2 U10.12
N17906339: R335.2 R336.2 U26.13
N17906381: R336.1 R337.2 U26.12
N17907326: R338.2 R339.2 U29.13
N17907351: R339.1 R340.2 U29.12
N17918762: D44.1 R341.2 R342.1
N17918800: Q31.1 R342.2
N17919694: C376.2 Q32.1 R344.2
N17920327: C377.2 Q33.1 R346.2
N17947557: D43.4 R134.2
N17948062: D43.2 R348.2
N18031326: R206.1 U19.31
N18080998: MH1.1 MH1.2 MH1.3 MH1.4 MH1.5 MH1.6 MH1.7 MH1.8 MH1.9(HOLE)
N18081006: MH2.1 MH2.2 MH2.3 MH2.4 MH2.5 MH2.6 MH2.7 MH2.8 MH2.9(HOLE)
N18081112: MH3.1 MH3.2 MH3.3 MH3.4 MH3.5 MH3.6 MH3.7 MH3.8 MH3.9(HOLE)
N18081120: MH4.1 MH4.2 MH4.3 MH4.4 MH4.5 MH4.6 MH4.7 MH4.8 MH4.9(HOLE)
N18115892: C361.1 C362.1 R349.1 U21.2 U21.4
N18121133: C359.1 C360.1 R320.1 U21.70 U21.72 U21.74
N18177282: R351.2 U9.7
N18177600: R353.2 U10.7
N18177766: R355.2 U26.7
N18177976: R357.2 U29.7
N18179902: C378.1 U22.1(VDD)
N18180321: R250.2 U22.9
N18180375: R248.2 U22.11
N18180517: R360.2 U22.14
N18180676: C379.2 U22.16
N25391738: C343.1 U23.12
N25392270: C339.1 U23.19
N25392272: C340.1 U23.10(VREF)
N25392276: C338.1 U23.20
N25392525: C344.1 U23.11
N25392529: R260.2 U23.1
N25392543: R261.2 U23.5
N25392545: R262.2 U23.6
N25392559: R263.2 U23.7
N25392573: R264.2 U23.8
N25392575: R265.2 U23.28
N25392589: R266.2 U23.27
N174312303: R25.2 U5.4
N175432600: Q12.3 R134.1

Pads without a net: J2 20 22 24 26 28 29 31 35 37 40 42 44 46 48 56 58 59 60 61 63 66 69; J4 C6; J18 4; J21 5 6 8 9; J23 1; J24 1 9 14; M1 1; M2 1; M3 1; M4 1; M5 1; M6 1; U1 4 5 22 23 24 25 26 27 28 29 30 31 32 33 34 35 36 37 38 39 43 44 47 48 49 50 51 52 53 54 55 56 61 62 63 64 67 68 72 73 74 75 76 77 78 79 80 81 82 83 84 85 86 87 88 89 90 91 101 102 103 104 105 106 107 108 109 110 111 112 113 114 115 116 117 118 119 120 175 176 177 178 179 180 191 192 193 194 195 196 197 198 199 200 201 202 203 204 205 206 207 208 209 210 213 217 226 238 242 243 244 247 248 251 253; U4 4; U8 2 8 9 10 11 14 15 20 22 24 25 26 27 29 30 50 51 52 53 54 55 56 59; U9 8 9 11; U10 8 9 11; U11 3 4 6 7 32 33 34 35 36 40 41 52 54 55 56 57 60 61 62 63 68 69 70 71 72 73 74 75 76 77 97 98 99 116 117; U13 3 4 6 7 32 33 34 35 36 40 41 52 54 55 56 57 60 61 62 63 68 69 70 71 72 73 74 75 76 77 97 98 99 116 117; U14 12 14 24 25 26 27 28 29 30 31 33 35 37 45 47; U15 1 2 3 4 5 6 7 14 15 16 17 18 19 22; U21 6 7 8 9 10 12 13 14 15 16 17 18 20 22 23 24 25 26 28 29 30 31 32 34 35 36 37 38 40 42 44 46 48 50 52 53 54 55 56 58 67 68; U22 2 8 15 17 19 21 24; U23 9 14 15 23 24 25; U24 A3 C1 C2 C3 D1 D2 D3 F4 H3 K3; U26 8 9 11; U29 8 9 11

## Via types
v1: diameter 0.356, hole 0.203, TOP to BOTTOM, 3161 vias
v2: diameter 0.61, hole 0.305, TOP to BOTTOM, 733 vias

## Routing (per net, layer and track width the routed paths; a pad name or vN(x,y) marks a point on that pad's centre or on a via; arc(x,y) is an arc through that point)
1V2_PLL: length 4.8
  TOP w0.254: U11.113 v1(120.51,27.16)
  BOTTOM w0.508: v1(120.51,27.16) 119.57,27.16 C153.1 118.67,27.15 C152.1 118.35,27.48 FB13.2
1V2_PLL1: length 4.8
  TOP w0.254: U13.113 v1(36.06,27.02)
  BOTTOM w0.508: FB22.2 33.9,27.34 C212.1 34.22,27.01 C213.1 35.12,27.02 v1(36.06,27.02)
1V2A_V1: length 8.3
  TOP w0.254: U11.14 128.36,18.58 v1(128.37,18.57) ; v1(125.88,18.56) 125.88,18.58 125.96,18.65 U11.8
  BOTTOM w0.508: v1(128.37,18.57) 125.89,18.57 v1(125.88,18.56) 124.96,18.56 C162.1 123.95,18.56 C161.1 123.66,18.85 FB15.2
1V2A_V2: length 10
  TOP w0.254: v1(133.16,18.47) U11.26 ; U11.20 130.76,18.54 v1(130.77,18.53)
  BOTTOM w0.508: FB16.2 136.49,16.97 C163.1 135.54,16.97 C164.1 134.38,17.25 v1(133.16,18.47) 133.1,18.53 v1(130.77,18.53)
1V2A_V3: length 20.7
  TOP w0.254: U11.38 138.22,23.16 138.22,23.16 v1(138.26,23.16) ; v2(135.16,33.9) 135.16,33.9 U11.66
  TOP w0.508: v1(138.26,23.16) v1(138.61,22.81) 138.76,22.66 C166.1 140.36,21.75 C165.1 140.03,21.41 FB17.2
  BOTTOM w0.508: v1(138.61,22.81) v1(138.26,23.16) 137.5,23.92 137.5,32.98 136.58,33.9 v2(135.16,33.9)
1V2A_V4: length 5.8
  TOP w0.254: U11.92 v1(124.76,36.28)
  BOTTOM w0.508: FB12.2 123.39,36.05 C150.1 124.76,36.85 v1(124.76,36.28) 125.23,36.28 125.23,36.28 C151.1
1V2A_V5: length 8.3
  TOP w0.254: U13.8 41.51,18.51 41.43,18.44 v1(41.43,18.42) ; U13.14 43.91,18.44 v1(43.92,18.43)
  BOTTOM w0.508: FB21.2 39.21,18.71 C210.1 39.5,18.42 C211.1 40.51,18.42 v1(41.43,18.42) 41.44,18.43 v1(43.92,18.43)
1V2A_V6: length 10
  TOP w0.254: v1(48.71,18.33) U13.26 ; U13.20 46.31,18.4 v1(46.32,18.39)
  BOTTOM w0.508: FB24.2 52.04,16.83 C221.1 51.09,16.83 C222.1 49.93,17.11 v1(48.71,18.33) 48.65,18.39 v1(46.32,18.39)
1V2A_V7: length 20.6
  TOP w0.254: v1(53.81,22.54) v1(53.81,23.02) 53.78,23.02 U13.38 ; U13.66 v2(50.71,33.76)
  TOP w0.508: FB25.2 56.74,22.4 C223.1 56.41,22.74 C224.1 53.82,22.74 53.81,22.75
  BOTTOM w0.508: v1(53.81,22.54) 53.81,23.02 v1(53.81,23.02) 53.81,23.34 53.05,24.1 53.05,32.84 52.14,33.76 v2(50.71,33.76)
1V2A_V8: length 5.8
  TOP w0.254: U13.92 v1(40.31,36.14)
  BOTTOM w0.508: FB26.2 38.94,35.91 C225.1 40.31,36.71 v1(40.31,36.14) 40.78,36.14 40.78,36.14 C226.1
1V2D: length 70.3
  TOP w0.254: U11.102 v1(122.7,31.56) ; U11.93 v1(124.36,34.02) ; U11.124 v1(122.7,22.76) ; U11.59 v1(136.01,31.56) ; U11.5 v1(124.76,20.71) ; U11.112 v1(122.7,27.56) ; U11.53 v1(136.01,29.16) ; U11.78 v1(130.36,34.02) ; U11.80 v1(129.56,34.02) ; U11.114 v1(122.7,26.76) ; U11.43 v1(136.01,25.16) ; U11.48 v1(136.01,27.16)
  TOP w0.381: U11.65 135.61,34.38 135.8,34.18 v2(135.8,32.42)
  BOTTOM w0.508: C159.1 v1(136.01,27.16) ; C159.1 C158.1 v1(136.01,25.16) ; C159.1 C155.1 ; C160.1 135.1,32.43 ; C160.1 v1(136.01,31.56) ; C160.1 C155.1 ; 135.1,32.43 135.8,32.43 v2(135.8,32.42) ; 135.1,32.43 131.72,32.43 131.12,33.02 C154.1 ; 123.85,22.77 123.85,22.76 v1(122.7,22.76) ; 123.85,22.77 123.85,21.61 v1(124.76,20.71) 125.48,19.99 136.17,19.99 136.18,20 FB14.2 ; 123.85,22.77 C156.1 ; v1(122.7,27.56) 122.7,27.18 ; 122.7,27.18 v1(122.7,26.76) ; 122.7,27.18 123.81,27.18 C156.1 ; C155.1 v1(136.01,29.16) ; C157.1 v1(124.36,34.02) ; C157.1 124.16,33.02 v1(122.7,31.56) 123.85,30.41 C156.1 ; C157.1 124.36,33.02 C154.1 ; 130.01,34.02 129.99,34 C154.1 ; 130.01,34.02 v1(129.56,34.02) ; 130.01,34.02 v1(130.36,34.02)
1V2D1: length 70.3
  TOP w0.254: U13.112 v1(38.25,27.42) ; U13.78 v1(45.91,33.88) ; U13.43 v1(51.56,25.02) ; U13.114 v1(38.25,26.62) ; U13.5 v1(40.31,20.57) ; U13.59 v1(51.56,31.42) ; U13.93 v1(39.91,33.88) ; U13.48 v1(51.56,27.02) ; U13.102 v1(38.25,31.42) ; U13.124 v1(38.25,22.62) ; U13.80 v1(45.11,33.88) ; U13.53 v1(51.56,29.02)
  TOP w0.381: v2(51.35,32.28) 51.35,34.04 51.16,34.24 U13.65
  BOTTOM w0.508: C214.1 46.68,32.88 47.27,32.29 50.66,32.29 ; C214.1 45.54,33.86 45.56,33.88 ; C214.1 C215.1 ; C218.1 39.36,27.04 38.25,27.04 ; C218.1 39.4,22.63 ; C218.1 39.4,30.27 v1(38.25,31.42) 39.71,32.88 C215.1 ; 39.4,22.63 39.4,21.47 v1(40.31,20.57) 41.03,19.85 51.72,19.85 51.73,19.86 FB23.2 ; 39.4,22.63 39.4,22.62 v1(38.25,22.62) ; v1(45.11,33.88) 45.56,33.88 ; 45.56,33.88 v1(45.91,33.88) ; v1(51.56,25.02) C220.1 C216.1 ; v1(38.25,27.42) 38.25,27.04 ; 38.25,27.04 v1(38.25,26.62) ; C217.1 C219.1 ; C217.1 C216.1 ; C217.1 v1(51.56,29.02) ; C219.1 50.66,32.29 ; C219.1 v1(51.56,31.42) ; C215.1 v1(39.91,33.88) ; v2(51.35,32.28) 51.35,32.29 50.66,32.29 ; C216.1 v1(51.56,27.02)
3V3A_AHD1: length 48.4
  TOP w0.254: U11.17 v1(129.56,20.71) ; U11.11 v1(127.16,20.71) ; U11.91 v1(125.16,33.95) ; U11.23 v1(131.96,20.71) ; U11.67 134.76,34.36 134.57,34.18 v1(134.57,33.2) ; U11.37 v1(136.01,22.76) ; U11.29 v1(134.36,20.71) ; U11.39 v1(136.01,23.56)
  BOTTOM w0.508: v1(125.16,33.95) 125.18,33.92 C141.1 126.02,34.16 126.53,34.67 130.75,34.67 132.21,33.21 134.56,33.21 v1(134.57,33.2) 134.58,33.21 136.05,33.21 136.66,32.6 136.66,24.21 v1(136.01,23.56) ; v1(127.16,20.71) C138.1 127.35,21.5 129.56,21.5 ; C142.1 134.35,21.5 C140.1 ; C142.1 v1(131.96,20.71) ; C142.1 129.56,21.5 ; FB10.2 134.74,21.51 ; 134.74,21.51 C140.1 ; 134.74,21.51 135.1,21.87 C139.1 v1(136.01,23.56) ; 129.56,21.5 v1(129.56,20.71) ; v1(136.01,23.56) v1(136.01,22.76) ; v1(134.36,20.71) C140.1
3V3A_AHD2: length 48.4
  TOP w0.254: U13.23 v1(47.51,20.57) ; U13.11 v1(42.71,20.57) ; U13.67 50.31,34.22 50.12,34.04 v1(50.12,33.06) ; U13.91 v1(40.71,33.81) ; U13.37 v1(51.56,22.62) ; U13.39 v1(51.56,23.42) ; U13.29 v1(49.91,20.57) ; U13.17 v1(45.11,20.57)
  BOTTOM w0.508: 45.11,21.36 C199.1 ; 45.11,21.36 v1(45.11,20.57) ; 45.11,21.36 42.9,21.36 C198.1 v1(42.71,20.57) ; C199.1 v1(47.51,20.57) ; C199.1 49.9,21.36 C202.1 ; 50.3,21.37 C202.1 ; 50.3,21.37 50.66,21.73 C200.1 v1(51.56,23.42) ; 50.3,21.37 FB19.2 ; C202.1 v1(49.91,20.57) ; v1(51.56,22.62) v1(51.56,23.42) ; v1(51.56,23.42) 52.21,24.07 52.21,32.46 51.6,33.07 50.13,33.07 v1(50.12,33.06) 50.12,33.07 47.76,33.07 46.3,34.53 42.08,34.53 41.58,34.02 C201.1 40.74,33.78 v1(40.71,33.81)
3V3D_AHD1: length 68.4
  TOP w0.254: U11.79 v1(129.96,36.15) ; U11.128 v1(120.51,21.11) ; U11.58 v1(138.2,31.16) ; U11.123 v1(120.51,23.16) ; U11.51 v1(138.2,28.36) ; U11.96 v1(123.11,34.02) ; U11.42 v1(138.2,24.76) ; U11.100 v1(120.51,32.36) ; U11.107 v1(120.51,29.56) ; U11.64 v1(138.2,33.61) ; U11.2 v1(123.56,20.71) ; U11.115 v1(120.51,26.36)
  TOP w0.381: R86.1 141.48,25.43 v1(141.48,25.43)
  BOTTOM w0.508: C148.1 121.17,23.13 121.17,20.71 ; C148.1 121.13,26.36 C144.1 ; C148.1 v1(120.51,23.16) ; v1(141.48,25.43) 139.04,25.43 ; 139.04,25.43 139.04,28.35 C146.1 ; 139.04,25.43 138.87,25.43 v1(138.2,24.76) ; FB11.2 139.03,31.94 ; 139.03,31.94 139.03,31.13 139.02,31.12 ; 139.03,31.94 139.03,33.54 C149.1 ; C144.1 v1(120.51,26.36) ; C144.1 121.16,26.4 C147.1 ; C149.1 138.95,34.91 137.71,36.15 v1(129.96,36.15) 129.95,36.14 C145.1 124.87,35.44 123.44,34.02 v1(123.11,34.02) 122.2,34.02 C143.1 121.81,33.67 v1(120.51,32.36) 120.51,30.63 121.16,29.98 C147.1 ; C149.1 v1(138.2,33.61) ; 121.17,20.71 120.91,20.71 v1(120.51,21.11) ; 121.17,20.71 v1(123.56,20.71) ; C147.1 v1(120.51,29.56) ; C146.1 139.02,31.12 ; C146.1 v1(138.2,28.36) ; 139.02,31.12 138.98,31.16 v1(138.2,31.16)
3V3D_AHD2: length 73.5
  TOP w0.254: U13.58 v1(53.75,31.02) ; U13.2 v1(39.11,20.57) ; U13.115 v1(36.06,26.22) ; U13.123 v1(36.06,23.02) ; U13.51 v1(53.75,28.22) ; U13.79 v1(45.51,36.01) ; U13.100 v1(36.06,32.22) ; U13.64 v1(53.75,33.47) ; U13.42 v1(53.75,24.62) ; U13.128 v1(36.06,20.97) ; U13.96 v1(38.66,33.88) ; U13.107 v1(36.06,29.42)
  TOP w0.381: R110.1 v1(57.01,26.65) ; v1(57.06,27.66) 57.06,27.66 R107.1 ; R106.2 v1(57.09,28.65) ; v1(57.03,25.29) 57.03,25.29 R109.1
  BOTTOM w0.508: C208.1 v1(36.06,23.02) ; C208.1 36.72,22.99 36.72,20.57 ; C208.1 36.69,26.22 C204.1 ; C209.1 54.59,28.21 54.59,25.29 ; C209.1 54.58,30.98 ; C209.1 v1(53.75,28.22) ; v1(53.75,24.62) 54.42,25.29 54.59,25.29 ; 36.72,20.57 36.46,20.57 v1(36.06,20.97) ; 36.72,20.57 v1(39.11,20.57) ; 54.58,31.8 FB20.2 ; 54.58,31.8 54.58,30.99 54.58,30.98 ; 54.58,31.8 54.58,33.4 C205.1 ; C204.1 36.71,26.26 C206.1 ; C204.1 v1(36.06,26.22) ; C205.1 54.5,34.77 53.26,36.01 v1(45.51,36.01) 45.49,36 C207.1 41.65,35.28 40.88,34.51 39.29,34.51 v1(38.66,33.88) 38.31,33.53 C203.1 37.36,33.53 v1(36.06,32.22) 36.06,31.67 36.21,31.52 36.21,30.34 36.71,29.84 C206.1 ; C205.1 v1(53.75,33.47) ; 54.58,30.98 54.53,31.02 v1(53.75,31.02) ; C206.1 v1(36.06,29.42) ; v1(57.09,28.65) 57.06,28.62 v1(57.06,27.66) 57.06,26.7 v1(57.01,26.65) 57.07,26.6 57.07,25.32 v1(57.03,25.29) 54.59,25.29
